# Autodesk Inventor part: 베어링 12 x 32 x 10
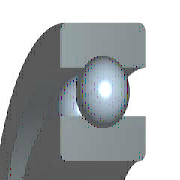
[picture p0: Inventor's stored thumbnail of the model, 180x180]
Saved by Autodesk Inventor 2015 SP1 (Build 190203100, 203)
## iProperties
IsCustomPart: 1
Created: 2012-02
Part Number: 베어링 12 x 32 x 10
Material: 강철, 연강
Description: 깊은 그루브 볼 베어링
Document SubType Name: Modeling
Standard: KS B 2023
Designer: test
Standards Organization: KS
Language: ko-KR
Size Designation: 6201 - 12 x 32 x 10
Categories: <MemberInstance><Categories><Category DisplayName="샤프트 부품" InternalName="7f7aeb1f-a693-4053-b835-cee3144e0d98" Mnemonic="SHFT"><Category DisplayName="베어링" Inter
Density: 1 g/cm^3
Appearance: 노란색
Author: test
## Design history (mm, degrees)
sketch "스케치" dims "d0" = 5.2 (= -0.26 x WD + 0.26 x BD)
  geometry: L1 (2.4, 11)-(7.6, 11); L2 (5, 11)-(5, 8.4); L3 (5, 11)-(5, 13.6); L4 (3.068, 9.26)-(0, 9.26); L5 (0, 6)-(10, 6); L6 (3.068, 12.74)-(0, 12.74); L7 (0, 16)-(10, 16); L8 (10, 6)-(10, 9.26); L9 (6.932, 9.26)-(10, 9.26); L10 (6.932, 12.74)-(10, 12.74); L11 (10, 16)-(10, 12.74); L12 (-1.4, 0)-(8.4, 0) reference; L13 (0, -0.3)-(0, 5.3) reference
  constraints: 22 end point, 4 point on line, 2 collinear, 2 perpendicular, 2 symmetric about line, 1 midpoint, 1 parallel, 14 other
  dimensions: "d9" = 12 diameter of L5 L12 (= WD); "d11" = 32 diameter of L7 L12 (= BD); "d12" = 10 distance between parallel lines of L8 L13 (= KB); "d13" = 18.52 diameter of L9 L12 (= 0.326 x BD + 0.674 x WD)
revolve "본체" stored, may be unused: angle "d6" = 90 deg
revolve "볼" stored, may be unused: angle "d7" = 90 deg
pattern_circular "IDS_ARRAYBALL[SIMPL:T]" dims angle "d3" = 360 deg
body "Solid1"
fillet "모깎기1" dims "d1" = 0.6 (= KRS)
other parameters: "WD" = 12 [user parameter; used in 5 equation terms], "BD" = 32 [user parameter; used in 5 equation terms], "KB" = 10 [user parameter; used in 1 equation term], "KRS" = 0.6 [user parameter; used in 1 equation term], "d4" = 0, "d5" = 0, "d8" = 0, "d14" = 0, "d15" = 0, "BBA" = 0 [user parameter], "BC0" = 3100000 [user parameter], "BC" = 6890000 [user parameter], "BR" = 16 (= 0.5 x BD) [user parameter], "WR" = 6 (= 0.5 x WD) [user parameter]
